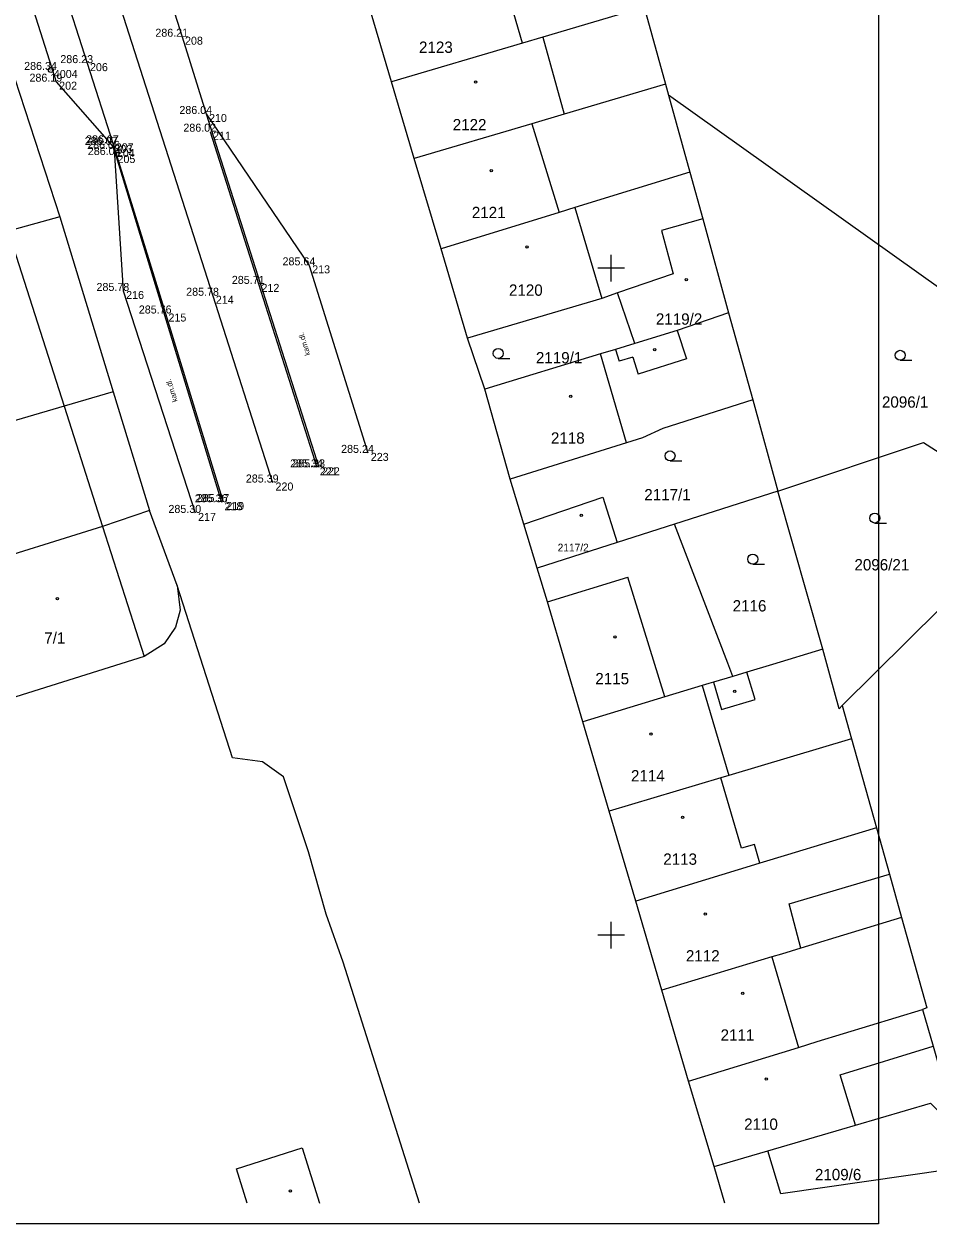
# Model space of a CAD drawing. Extents: x -599970 to -599524, y -1154772 to -1154457.
# Drawn here: x -599644 to -599576.2, y -1154771.7 to -1154681.7 of the extents above; entities that cross this region are included whole.
import ezdxf

# ---------------------------------------------------------------- set-up
doc = ezdxf.new("R2010")
doc.units = 0
for name, color, linetype in [('Z-KATASTRALNI MAPA', 7, 'Continuous'), ('Z-KRIZKY CTVERCOVE SITE', 7, 'Continuous'), ('Z-PEVNE BODY-CISLO', 7, 'Continuous'), ('Z-PEVNE BODY-VYSKA', 7, 'Continuous'), ('Z-PEVNE BODY-ZNACKA', 7, 'Continuous'), ('Z-PODROBNE BODY', 7, 'Continuous'), ('Z-PODROBNE BODY-CISLO', 7, 'Continuous'), ('Z-PODROBNE BODY-VYSKA', 7, 'Continuous'), ('Z-POPISY OBJEKTU A ZPEVNENYCH PLOCH', 7, 'Continuous'), ('Z-RAM ROZPISKA', 7, 'Continuous'), ('Z-VODOROVNE ZNACENI', 7, 'Continuous'), ('Z-ZPEVNENE PLOCHY', 7, 'Continuous')]:
    doc.layers.add(name, color=color, linetype=linetype)

msp = doc.modelspace()

# ---------------------------------------------------------------- linework, layer by layer
at = {"layer": 'Z-KATASTRALNI MAPA'}
for p, q in [((-599606.65, -1154683.13), (-599607.71, -1154679.5)), ((-599616.47, -1154686.03), (-599618.2, -1154680.21)), ((-599597.53, -1154680.43), (-599605.12, -1154682.67)), ((-599597.53, -1154680.43), (-599595.94, -1154686.2)), ((-599605.12, -1154682.67), (-599603.52, -1154688.45)), ((-599644.7, -1154685.8), (-599641.32, -1154696.15)), ((-599614.76, -1154691.78), (-599616.47, -1154686.03)), ((-599595.94, -1154686.2), (-599603.52, -1154688.45)), ((-599595.94, -1154686.2), (-599595.71, -1154687.03)), ((-599575.13, -1154701.69), (-599595.71, -1154687.03)), ((-599595.71, -1154687.03), (-599594.12, -1154692.8)), ((-599605.96, -1154689.17), (-599603.91, -1154695.82)), ((-599612.75, -1154698.54), (-599614.76, -1154691.78)), ((-599594.12, -1154692.8), (-599593.15, -1154696.3)), ((-599602.72, -1154695.45), (-599600.7, -1154702.26)), ((-599641.32, -1154696.15), (-599645.18, -1154697.21)), ((-599641.32, -1154696.15), (-599637.32, -1154709.26)), ((-599593.15, -1154696.3), (-599591.21, -1154703.34)), ((-599645.18, -1154697.21), (-599640.99, -1154710.34)), ((-599610.76, -1154705.25), (-599612.75, -1154698.54)), ((-599598.24, -1154705.64), (-599599.52, -1154701.85)), ((-599591.21, -1154703.34), (-599589.4, -1154709.86)), ((-599595.05, -1154704.67), (-599594.35, -1154706.78)), ((-599609.48, -1154709.06), (-599610.76, -1154705.25)), ((-599598.85, -1154713.08), (-599600.8, -1154706.42)), ((-599599.67, -1154706.08), (-599599.4, -1154706.97)), ((-599608.466, -1154706.76), (-599607.591, -1154706.76)), ((-599598.38, -1154706.66), (-599599.4, -1154706.97)), ((-599598.38, -1154706.66), (-599597.98, -1154707.93)), ((-599594.35, -1154706.78), (-599597.98, -1154707.93)), ((-599578.346, -1154706.9), (-599577.471, -1154706.9)), ((-599637.32, -1154709.26), (-599640.99, -1154710.34)), ((-599637.32, -1154709.26), (-599634.61, -1154718.17)), ((-599607.58, -1154715.81), (-599609.48, -1154709.06)), ((-599589.4, -1154709.86), (-599587.51, -1154716.71)), ((-599640.99, -1154710.34), (-599638.12, -1154719.35)), ((-599587.51, -1154716.71), (-599576.61, -1154713.05)), ((-599576.61, -1154713.05), (-599552.63, -1154728.55)), ((-599595.596, -1154714.44), (-599594.721, -1154714.44)), ((-599606.55, -1154719.18), (-599607.58, -1154715.81)), ((-599587.51, -1154716.71), (-599595.25, -1154719.19)), ((-599584.15, -1154728.56), (-599587.51, -1154716.71)), ((-599634.61, -1154718.17), (-599638.12, -1154719.35)), ((-599632.53, -1154723.79), (-599634.61, -1154718.17)), ((-599580.257, -1154719.1), (-599579.382, -1154719.1)), ((-599638.12, -1154719.35), (-599634.99, -1154729.1)), ((-599605.54, -1154722.48), (-599606.55, -1154719.18)), ((-599595.25, -1154719.19), (-599599.56, -1154720.57)), ((-599599.56, -1154720.57), (-599605.54, -1154722.48)), ((-599589.397, -1154722.18), (-599588.522, -1154722.18)), ((-599604.77, -1154725), (-599598.75, -1154723.15)), ((-599595.99, -1154732.14), (-599598.75, -1154723.15)), ((-599575.36, -1154725.51), (-599582.69, -1154732.79)), ((-599589.22, -1154732.32), (-599589.84, -1154730.28)), ((-599593.18, -1154731.29), (-599591.2, -1154738.03)), ((-599592.35, -1154731.04), (-599591.73, -1154733.08)), ((-599591.73, -1154733.08), (-599589.22, -1154732.32)), ((-599582.69, -1154732.79), (-599581.99, -1154735.28)), ((-599600.15, -1154740.71), (-599602.12, -1154733.99)), ((-599581.99, -1154735.28), (-599591.2, -1154738.03)), ((-599581.99, -1154735.28), (-599580.13, -1154741.94)), ((-599590.23, -1154743.48), (-599591.78, -1154738.2)), ((-599598.17, -1154747.44), (-599600.15, -1154740.71)), ((-599580.13, -1154741.94), (-599583.68, -1154743.02)), ((-599589.27, -1154743.2), (-599590.23, -1154743.48)), ((-599588.86, -1154744.6), (-599589.27, -1154743.2)), ((-599583.68, -1154743.02), (-599586.79, -1154743.97)), ((-599589.27, -1154744.73), (-599598.17, -1154747.44)), ((-599596.2, -1154754.13), (-599598.17, -1154747.44)), ((-599587.96, -1154751.63), (-599585.96, -1154758.41)), ((-599594.2, -1154760.93), (-599596.2, -1154754.13)), ((-599582.84, -1154760.47), (-599575.88, -1154758.32)), ((-599581.69, -1154764.24), (-599582.84, -1154760.47)), ((-599592.3, -1154767.35), (-599594.2, -1154760.93)), ((-599592.3, -1154767.35), (-599588.27, -1154766.17))]:
    msp.add_line(p, q, dxfattribs=at)
for points in [[(-599605.12, -1154682.67), (-599606.65, -1154683.13), (-599616.47, -1154686.03)], [(-599603.52, -1154688.45), (-599605.96, -1154689.17), (-599614.76, -1154691.78)], [(-599594.12, -1154692.8), (-599602.72, -1154695.45), (-599603.91, -1154695.82), (-599612.75, -1154698.54)], [(-599593.15, -1154696.3), (-599596.23, -1154697.17), (-599595.35, -1154700.42), (-599599.52, -1154701.85)], [(-599599.52, -1154701.85), (-599600.7, -1154702.26), (-599610.76, -1154705.25)], [(-599591.21, -1154703.34), (-599595.05, -1154704.67), (-599598.24, -1154705.64)], [(-599598.24, -1154705.64), (-599599.67, -1154706.08), (-599600.8, -1154706.42), (-599609.48, -1154709.06)], [(-599589.4, -1154709.86), (-599596.14, -1154712.02), (-599597.66, -1154712.71), (-599598.85, -1154713.08), (-599607.58, -1154715.81)], [(-599640.99, -1154710.34), (-599653.61, -1154714.03), (-599657.79, -1154715.25)], [(-599606.55, -1154719.18), (-599600.64, -1154717.16), (-599599.56, -1154720.57)], [(-599638.12, -1154719.35), (-599648.07, -1154722.46), (-599650.19, -1154723.12)], [(-599590.89, -1154730.6), (-599591.27, -1154729.6), (-599595.25, -1154719.19)], [(-599602.12, -1154733.99), (-599604.77, -1154725), (-599605.54, -1154722.48)], [(-599632.53, -1154723.79), (-599632.29, -1154725.63), (-599632.66, -1154726.9), (-599633.49, -1154728.16), (-599634.99, -1154729.1), (-599649.01, -1154733.5)], [(-599614.36, -1154770.1), (-599620.08, -1154752.03), (-599621.36, -1154748.41), (-599622.69, -1154743.75), (-599624.56, -1154738.12), (-599626.13, -1154737), (-599628.37, -1154736.7), (-599632.53, -1154723.79)], [(-599584.15, -1154728.56), (-599587.93, -1154729.7), (-599589.84, -1154730.28), (-599590.89, -1154730.6)], [(-599582.69, -1154732.79), (-599582.93, -1154733.03), (-599583.62, -1154730.49), (-599584.15, -1154728.56)], [(-599590.89, -1154730.6), (-599592.35, -1154731.04), (-599592.69, -1154731.14), (-599593.18, -1154731.29), (-599595.99, -1154732.14), (-599602.12, -1154733.99)], [(-599591.2, -1154738.03), (-599591.78, -1154738.2), (-599600.15, -1154740.71)], [(-599580.13, -1154741.94), (-599579.16, -1154745.43), (-599578.25, -1154748.67)], [(-599586.79, -1154743.97), (-599588.86, -1154744.6), (-599589.27, -1154744.73)], [(-599585.8, -1154750.97), (-599586.67, -1154747.64), (-599579.16, -1154745.43)], [(-599578.25, -1154748.67), (-599585.8, -1154750.97), (-599587.24, -1154751.41), (-599587.96, -1154751.63), (-599596.2, -1154754.13)], [(-599578.25, -1154748.67), (-599576.36, -1154755.44), (-599576.67, -1154755.56)], [(-599594.2, -1154760.93), (-599585.96, -1154758.41), (-599584.58, -1154757.98), (-599576.67, -1154755.56)], [(-599576.67, -1154755.56), (-599575.88, -1154758.32), (-599574.78, -1154762.19)], [(-599576.09, -1154762.58), (-599574.57, -1154764.07), (-599571.5, -1154767.11), (-599587.3, -1154769.4), (-599588.27, -1154766.17)], [(-599588.27, -1154766.17), (-599582.73, -1154764.55), (-599581.69, -1154764.24), (-599576.09, -1154762.58)], [(-599627.27, -1154770.1), (-599628.09, -1154767.51), (-599623.16, -1154765.95), (-599621.85, -1154770.1)], [(-599591.49, -1154770.1), (-599592.3, -1154767.35)]]:
    msp.add_lwpolyline(points, dxfattribs=at)
for centre, radius in [((-599610.163, -1154686.04), 0.0875), ((-599608.993, -1154692.69), 0.0875), ((-599606.313, -1154698.4), 0.0875), ((-599594.383, -1154700.86), 0.0875), ((-599608.466, -1154706.385), 0.375), ((-599596.743, -1154706.1), 0.0875), ((-599578.346, -1154706.525), 0.375), ((-599603.033, -1154709.6), 0.0875), ((-599595.596, -1154714.065), 0.375), ((-599602.253, -1154718.53), 0.0875), ((-599580.256, -1154718.725), 0.375), ((-599589.396, -1154721.805), 0.375), ((-599641.503, -1154724.78), 0.0875), ((-599599.723, -1154727.64), 0.0875), ((-599590.743, -1154731.72), 0.0875), ((-599597.023, -1154734.92), 0.0875), ((-599594.653, -1154741.17), 0.0875), ((-599592.953, -1154748.42), 0.0875), ((-599590.143, -1154754.36), 0.0875), ((-599588.383, -1154760.79), 0.0875), ((-599624.043, -1154769.17), 0.0875)]:
    msp.add_circle(centre, radius, dxfattribs=at)
at = {"layer": 'Z-KRIZKY CTVERCOVE SITE'}
for p, q in [((-599600, -1154701), (-599600, -1154699)), ((-599599, -1154700), (-599601, -1154700)), ((-599600, -1154751), (-599600, -1154749)), ((-599599, -1154750), (-599601, -1154750))]:
    msp.add_line(p, q, dxfattribs=at)
at = {"layer": 'Z-PEVNE BODY-ZNACKA'}
for radius in [0.188, 0.188, 0.00896, 0.00896]:
    msp.add_circle((-599641.99, -1154685.13), radius, dxfattribs=at)
at = {"layer": 'Z-PODROBNE BODY'}
for p, q in [((-599632.16, -1154682.64), (-599632.16, -1154682.64)), ((-599639.28, -1154684.62), (-599639.28, -1154684.62)), ((-599641.59, -1154686.01), (-599641.59, -1154686.01)), ((-599630.36, -1154688.43), (-599630.36, -1154688.43)), ((-599630.06, -1154689.76), (-599630.06, -1154689.76)), ((-599637.45, -1154690.75), (-599637.45, -1154690.75)), ((-599637.35, -1154690.63), (-599637.35, -1154690.63)), ((-599637.27, -1154691.05), (-599637.27, -1154691.05)), ((-599637.22, -1154691.51), (-599637.22, -1154691.51)), ((-599622.63, -1154699.78), (-599622.63, -1154699.78)), ((-599626.43, -1154701.17), (-599626.43, -1154701.17)), ((-599636.57, -1154701.7), (-599636.57, -1154701.7)), ((-599629.85, -1154702.06), (-599629.85, -1154702.06)), ((-599633.4, -1154703.39), (-599633.4, -1154703.39)), ((-599618.24, -1154713.84), (-599618.24, -1154713.84)), ((-599622.06, -1154714.92), (-599622.06, -1154714.92)), ((-599621.9, -1154714.92), (-599621.9, -1154714.92)), ((-599625.38, -1154716.06), (-599625.38, -1154716.06)), ((-599629.2, -1154717.54), (-599629.2, -1154717.54)), ((-599629.07, -1154717.52), (-599629.07, -1154717.52)), ((-599631.18, -1154718.34), (-599631.18, -1154718.34))]:
    msp.add_line(p, q, dxfattribs=at)
at = {"layer": 'Z-RAM ROZPISKA'}
msp.add_lwpolyline([(-599876.98, -1154456.65), (-599579.98, -1154456.65), (-599579.98, -1154771.65), (-599876.98, -1154771.65)], close=True, dxfattribs=at)
at = {"layer": 'Z-VODOROVNE ZNACENI'}
for points in [[(-599694.02, -1154499.99), (-599689.54, -1154514.32), (-599685.46, -1154527.42), (-599683.24, -1154534.53), (-599677.91, -1154551.43), (-599673.26, -1154566.04), (-599670.15, -1154575.91), (-599664.69, -1154593.08), (-599661.63, -1154602.65), (-599657.71, -1154615.01), (-599654.33, -1154625.58), (-599650.3, -1154638.13), (-599646.03, -1154651.51), (-599641.58, -1154665.41), (-599629.85, -1154702.06), (-599625.38, -1154716.06)], [(-599697.63, -1154501.15), (-599693.46, -1154514.34), (-599689.12, -1154528.02), (-599685.9, -1154538.22), (-599681.17, -1154553.13), (-599676.65, -1154567.39), (-599673.59, -1154577), (-599671.31, -1154584.14), (-599668.11, -1154594.2), (-599666.34, -1154599.75), (-599661.15, -1154616.02), (-599657.79, -1154626.57), (-599653.82, -1154639.02), (-599649.52, -1154652.61), (-599645.03, -1154666.6), (-599639.28, -1154684.62), (-599637.35, -1154690.63), (-599633.4, -1154703.39)], [(-599630.06, -1154689.76), (-599626.43, -1154701.17)], [(-599626.43, -1154701.17), (-599622.06, -1154714.92)], [(-599633.4, -1154703.39), (-599629.07, -1154717.52)]]:
    msp.add_lwpolyline(points, dxfattribs=at)
at = {"layer": 'Z-ZPEVNENE PLOCHY'}
for points in [[(-599672.4, -1154589.48), (-599670.73, -1154594.81), (-599667.36, -1154605.26), (-599665.4, -1154611.41), (-599665.09, -1154612.38), (-599663.59, -1154616.97), (-599663.32, -1154617.94), (-599660.4, -1154627.02), (-599656.6, -1154638.85), (-599656.29, -1154639.8), (-599655.25, -1154643.15), (-599654.93, -1154644.12), (-599651.93, -1154653.5), (-599647.41, -1154667.76), (-599641.59, -1154686.01), (-599637.45, -1154690.75), (-599637.27, -1154691.05), (-599637.22, -1154691.51), (-599636.57, -1154701.7), (-599631.18, -1154718.34)], [(-599646.76, -1154636.94), (-599646.48, -1154637.9), (-599642.39, -1154650.64), (-599638.05, -1154664.15), (-599632.16, -1154682.64), (-599630.36, -1154688.43), (-599622.63, -1154699.78), (-599618.24, -1154713.84)], [(-599630.36, -1154688.43), (-599621.9, -1154714.92)], [(-599637.27, -1154691.05), (-599629.2, -1154717.54)]]:
    msp.add_lwpolyline(points, dxfattribs=at)

# ---------------------------------------------------------------- texts
at = {"layer": 'Z-KATASTRALNI MAPA'}
for s, height, p in [('2123', 0.85, (-599614.405, -1154683.85)), ('2122', 0.85, (-599611.878, -1154689.66)), ('2121', 0.85, (-599610.447, -1154696.24)), ('2120', 0.85, (-599607.665, -1154702.06)), ('2119/2', 0.85, (-599596.657, -1154704.23)), ('2119/1', 0.85, (-599605.646, -1154707.13)), ('2096/1', 0.85, (-599579.717, -1154710.45)), ('2118', 0.85, (-599604.521, -1154713.15)), ('2117/1', 0.85, (-599597.526, -1154717.4)), ('2117/2', 0.57, (-599604.015, -1154721.22)), ('2096/21', 0.85, (-599581.779, -1154722.65)), ('2116', 0.85, (-599590.901, -1154725.73)), ('7/1', 0.85, (-599642.483, -1154728.14)), ('2115', 0.85, (-599601.194, -1154731.19)), ('2114', 0.85, (-599598.521, -1154738.47)), ('2113', 0.85, (-599596.104, -1154744.72)), ('2112', 0.85, (-599594.407, -1154751.97)), ('2111', 0.85, (-599591.807, -1154757.91)), ('2110', 0.85, (-599590.044, -1154764.59)), ('2109/6', 0.85, (-599584.74, -1154768.37))]:
    msp.add_text(s, height=height, dxfattribs=at).set_placement(p)
at = {"layer": 'Z-PEVNE BODY-CISLO'}
msp.add_text(' 4004', height=0.6, dxfattribs=at).set_placement((-599641.99, -1154685.73))
at = {"layer": 'Z-PEVNE BODY-VYSKA'}
msp.add_text('286.34 ', height=0.6, dxfattribs=at).set_placement((-599643.99, -1154685.13))
at = {"layer": 'Z-PODROBNE BODY-CISLO'}
for s, p in [(' 208', (-599632.16, -1154683.24)), (' 206', (-599639.28, -1154685.22)), (' 202', (-599641.59, -1154686.61)), (' 210', (-599630.36, -1154689.03)), (' 211', (-599630.06, -1154690.36)), (' 203', (-599637.45, -1154691.35)), (' 207', (-599637.35, -1154691.23)), (' 204', (-599637.27, -1154691.65)), (' 205', (-599637.22, -1154692.11)), (' 213', (-599622.63, -1154700.38)), (' 212', (-599626.43, -1154701.77)), (' 216', (-599636.57, -1154702.3)), (' 214', (-599629.85, -1154702.66)), (' 215', (-599633.4, -1154703.99)), (' 223', (-599618.24, -1154714.44)), (' 221', (-599622.06, -1154715.52)), (' 222', (-599621.9, -1154715.52)), (' 220', (-599625.38, -1154716.66)), (' 218', (-599629.2, -1154718.14)), (' 219', (-599629.07, -1154718.12)), (' 217', (-599631.18, -1154718.94))]:
    msp.add_text(s, height=0.6, dxfattribs=at).set_placement(p)
at = {"layer": 'Z-PODROBNE BODY-VYSKA'}
for s, p in [('286.21 ', (-599634.16, -1154682.64)), ('286.23 ', (-599641.28, -1154684.62)), ('286.19 ', (-599643.59, -1154686.01)), ('286.04 ', (-599632.36, -1154688.43)), ('286.02 ', (-599632.06, -1154689.76)), ('286.07 ', (-599639.45, -1154690.75)), ('286.07 ', (-599639.35, -1154690.63)), ('286.06 ', (-599639.27, -1154691.05)), ('286.04 ', (-599639.22, -1154691.51)), ('285.64 ', (-599624.63, -1154699.78)), ('285.78 ', (-599638.57, -1154701.7)), ('285.71 ', (-599628.43, -1154701.17)), ('285.78 ', (-599631.85, -1154702.06)), ('285.76 ', (-599635.4, -1154703.39)), ('285.24 ', (-599620.24, -1154713.84)), ('285.34 ', (-599624.06, -1154714.92)), ('285.33 ', (-599623.9, -1154714.92)), ('285.39 ', (-599627.38, -1154716.06)), ('285.36 ', (-599631.2, -1154717.54)), ('285.37 ', (-599631.07, -1154717.52)), ('285.30 ', (-599633.18, -1154718.34))]:
    msp.add_text(s, height=0.6, dxfattribs=at).set_placement(p)
at = {"layer": 'Z-POPISY OBJEKTU A ZPEVNENYCH PLOCH'}
for p in [(-599622.55, -1154706.47), (-599632.49, -1154709.96)]:
    msp.add_text('kam.dl.', height=0.4, rotation=107.03717, dxfattribs=at).set_placement(p)

doc.saveas('drawing.dxf')
